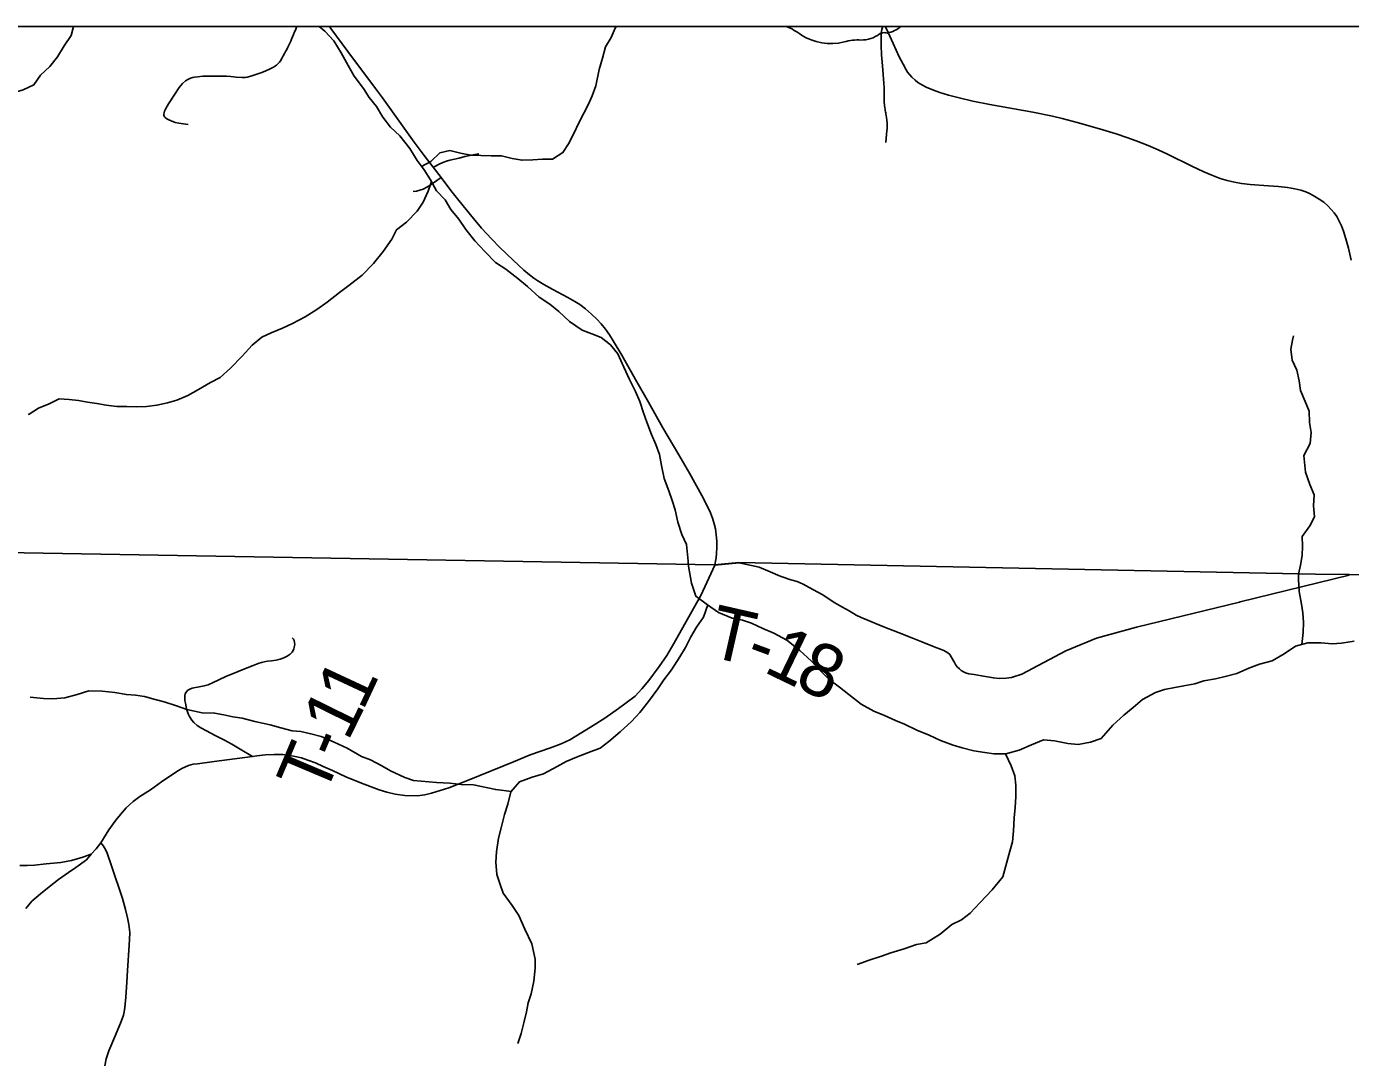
# Model space of a CAD drawing. Extents: x 0 to 191, y 0 to 55.
# Drawn here: x 186.002 to 187.422, y 53.609 to 54.72 of the extents above; entities that cross this region are included whole.
import ezdxf

# ---------------------------------------------------------------- set-up
doc = ezdxf.new("R2010")
doc.units = 0
for name, color, linetype in [('GM_X_Corporation', 7, 'Continuous'), ('GM_X_County_Road', 7, 'Continuous'), ('GM_X_Minor_River', 7, 'Continuous'), ('GM_X_State_Route', 7, 'Continuous'), ('GM_X_Township_Road', 7, 'Continuous'), ('GM_X_Township_Road_Text', 7, 'Continuous'), ('GM_X_Unincorporated', 7, 'Continuous')]:
    doc.layers.add(name, color=color, linetype=linetype)

msp = doc.modelspace()

# ---------------------------------------------------------------- linework, layer by layer
at = {"layer": 'GM_X_Corporation'}
msp.add_lwpolyline([(190.454, 54.7197), (184.1701, 54.7197), (184.1701, 53.923), (184.4114, 53.9192), (184.4129, 54.1665), (185.8476, 54.1564), (185.8681, 54.1568), (185.9791, 54.1551), (186.7401, 54.1422), (186.7662, 54.1447), (187.3845, 54.1319), (187.4205, 54.1315), (187.8766, 54.1257), (188.8023, 54.11), (189.605, 54.0923), (189.9218, 54.091), (189.9868, 54.0885), (190.0713, 54.0857), (190.1339, 54.0854), (190.3547, 54.0823), (190.439, 54.0815), (190.4406, 54.1842), (190.4414, 54.2285), (190.4414, 54.232)], close=True, dxfattribs=at)
msp.add_lwpolyline([(190.454, 54.7197), (184.1701, 54.7197), (184.1701, 53.923), (184.4114, 53.9192), (184.4129, 54.1665), (185.8476, 54.1564), (185.8681, 54.1568), (185.9791, 54.1551), (186.7401, 54.1422), (186.7662, 54.1447), (187.3845, 54.1319), (187.4205, 54.1315), (187.8766, 54.1257), (188.8023, 54.11), (189.605, 54.0923), (189.9218, 54.091), (189.9868, 54.0885), (190.0713, 54.0857), (190.1339, 54.0854), (190.3547, 54.0823), (190.439, 54.0815), (190.4406, 54.1842), (190.4414, 54.2285), (190.4414, 54.232)], close=True, dxfattribs=at)
for points in [[(187.8766, 54.1257), (187.4205, 54.1315), (187.3845, 54.1319), (186.7662, 54.1447), (186.7401, 54.1422), (185.9791, 54.1551), (185.8681, 54.1568), (185.8476, 54.1564), (184.4129, 54.1665), (184.4114, 53.9192), (184.1701, 53.923), (184.1701, 47.9197)], [(184.8319, 50.3472), (184.8438, 50.7018), (184.8438, 50.7041), (184.8504, 51.1664), (184.8504, 51.1691), (184.8564, 51.468), (185.0493, 51.466), (185.0519, 51.466), (185.737, 51.4587), (185.8223, 51.4579), (185.8471, 52.9493), (185.8472, 52.953), (185.8634, 53.9305), (185.8653, 54.0182), (185.8655, 54.0321), (185.8681, 54.1568), (185.9791, 54.1551), (186.7401, 54.1422), (186.7662, 54.1447), (187.3845, 54.1319), (187.4205, 54.1315), (187.8766, 54.1257)]]:
    msp.add_lwpolyline(points, dxfattribs=at)
at = {"layer": 'GM_X_County_Road'}
msp.add_line((186.4469, 54.5577), (186.4385, 54.5686), dxfattribs=at)
for points in [[(186.4385, 54.5686), (186.4288, 54.5812), (186.4181, 54.5957), (186.3839, 54.6431), (186.3765, 54.653), (186.3469, 54.693), (186.3288, 54.7175), (186.3273, 54.7197)], [(186.7403, 54.1417), (186.7412, 54.1461), (186.7417, 54.1494), (186.7423, 54.1542), (186.7426, 54.1605), (186.7425, 54.1674), (186.7419, 54.1743), (186.741, 54.1805), (186.7397, 54.186), (186.7379, 54.192), (186.7356, 54.1978), (186.7311, 54.2075), (186.7266, 54.2164), (186.7134, 54.2403), (186.7084, 54.249), (186.7017, 54.2602), (186.6961, 54.2698), (186.6848, 54.2891), (186.6693, 54.3167), (186.6553, 54.3409), (186.6406, 54.3669), (186.6315, 54.3825), (186.6274, 54.3888), (186.6231, 54.3949), (186.6184, 54.4008), (186.6137, 54.4058), (186.6083, 54.411), (186.6016, 54.4167), (186.5956, 54.4212), (186.5904, 54.4246), (186.5828, 54.429), (186.5668, 54.4374), (186.5571, 54.4428), (186.5507, 54.4466), (186.5462, 54.4498), (186.5418, 54.4531), (186.5356, 54.4583), (186.5242, 54.4688), (186.5095, 54.483), (186.5012, 54.4914), (186.4903, 54.5033), (186.4815, 54.5137), (186.4658, 54.5329), (186.4575, 54.5438), (186.4469, 54.5577)], [(186.082, 53.8438), (186.0907, 53.8578), (186.098, 53.868), (186.1032, 53.8742), (186.1091, 53.8814), (186.1168, 53.8881), (186.124, 53.8935), (186.1352, 53.9007), (186.1471, 53.9091), (186.1634, 53.9202), (186.1689, 53.9235), (186.1759, 53.9266), (186.1812, 53.928), (186.1858, 53.9286), (186.2036, 53.9311), (186.2448, 53.9365), (186.2493, 53.937), (186.2585, 53.9382), (186.268, 53.9387), (186.2772, 53.9385), (186.2888, 53.9366), (186.2971, 53.9349), (186.304, 53.9326), (186.3123, 53.9296), (186.3203, 53.9257), (186.3304, 53.9212), (186.3449, 53.9146), (186.3614, 53.9077), (186.3805, 53.9006), (186.3886, 53.898), (186.3978, 53.896), (186.408, 53.8944), (186.4214, 53.8943), (186.4293, 53.8954), (186.4365, 53.8971), (186.455, 53.9026), (186.4771, 53.9114), (186.5245, 53.9307), (186.5425, 53.938), (186.5642, 53.9456), (186.5757, 53.9501), (186.5849, 53.9544), (186.5979, 53.9622), (186.61, 53.9698), (186.6224, 53.9776), (186.6371, 53.988), (186.6454, 53.9938), (186.6548, 54.0013), (186.6622, 54.0091), (186.6696, 54.0178), (186.6807, 54.0328), (186.6888, 54.0446), (186.6965, 54.0577), (186.7048, 54.0723), (186.7253, 54.1092), (186.7403, 54.1417)], [(186.0017, 53.7734), (186.0082, 53.781), (186.0172, 53.7892), (186.0267, 53.7967), (186.0366, 53.8044), (186.0472, 53.812), (186.0551, 53.8172), (186.0665, 53.8255), (186.0718, 53.8315), (186.0771, 53.8373), (186.082, 53.8438)], [(186.0718, 53.8315), (186.0627, 53.8283), (186.0506, 53.8249), (186.0391, 53.8228), (186.0235, 53.8212), (186.011, 53.8198), (186.003, 53.8194), (185.9951, 53.8196)]]:
    msp.add_lwpolyline(points, dxfattribs=at)
at = {"layer": 'GM_X_Minor_River'}
for points in [[(186.0526, 54.7197), (186.0502, 54.71), (186.0428, 54.6989), (186.0357, 54.6871), (186.0275, 54.6767), (186.0174, 54.6675), (186.0103, 54.6572), (185.9986, 54.6517), (185.9869, 54.6481), (185.9745, 54.6415), (185.9621, 54.6357), (185.9523, 54.6318), (185.9413, 54.6286), (185.9229, 54.6204), (185.9108, 54.6134), (185.9, 54.6023), (185.8925, 54.5889), (185.8801, 54.5808), (185.8681, 54.5738), (185.8568, 54.5645), (185.8535, 54.5603)], [(186.3162, 54.7197), (186.3223, 54.7146), (186.3319, 54.7041), (186.3396, 54.6913), (186.3473, 54.6777), (186.3538, 54.6664), (186.3638, 54.6533), (186.3699, 54.6435), (186.3776, 54.6337), (186.3845, 54.6224), (186.3926, 54.6115), (186.4025, 54.6022), (186.4132, 54.5886), (186.4213, 54.5759), (186.4286, 54.5657), (186.4355, 54.5552), (186.4421, 54.5435), (186.4513, 54.5337), (186.4574, 54.5232), (186.4658, 54.513), (186.4735, 54.5018), (186.4831, 54.4897), (186.4938, 54.4781), (186.5053, 54.4665), (186.5163, 54.4594), (186.5293, 54.4493), (186.5396, 54.4407), (186.5522, 54.4291), (186.5636, 54.4217), (186.5732, 54.4139), (186.5846, 54.403), (186.598, 54.3937), (186.6086, 54.39), (186.6185, 54.386), (186.6284, 54.3781), (186.6365, 54.3684), (186.6427, 54.354), (186.6489, 54.3408), (186.6554, 54.328), (186.6601, 54.3174), (186.664, 54.3053), (186.6675, 54.2951), (186.6725, 54.2819), (186.6772, 54.271), (186.6811, 54.2604), (186.6831, 54.2486), (186.6859, 54.2346), (186.6909, 54.2214), (186.6948, 54.2112)], [(186.4258, 54.5696), (186.4357, 54.5749), (186.4455, 54.5841), (186.4564, 54.5865), (186.4678, 54.5836), (186.4788, 54.5815), (186.4894, 54.5813), (186.5004, 54.581), (186.5117, 54.5808), (186.5231, 54.5779), (186.5337, 54.5761), (186.5454, 54.5767), (186.5556, 54.5772), (186.5662, 54.5773), (186.5775, 54.5843), (186.5835, 54.5938), (186.589, 54.6042), (186.595, 54.6171), (186.6046, 54.6355), (186.6087, 54.6454), (186.6127, 54.6561), (186.6164, 54.6736), (186.62, 54.6858), (186.6233, 54.6979), (186.6292, 54.7079), (186.6337, 54.7178), (186.6348, 54.7197)], [(186.4366, 54.5532), (186.433, 54.543), (186.4278, 54.5312), (186.4211, 54.5216), (186.4099, 54.5097), (186.399, 54.5016), (186.3942, 54.4916), (186.3848, 54.4782), (186.3744, 54.4652), (186.3624, 54.4529), (186.3481, 54.4417), (186.338, 54.4344), (186.3248, 54.424), (186.3136, 54.4159), (186.3012, 54.4081), (186.2876, 54.4011), (186.2767, 54.3961), (186.2646, 54.391), (186.2545, 54.3863), (186.2443, 54.3778), (186.2335, 54.3659), (186.2211, 54.3529), (186.2099, 54.3432), (186.1997, 54.3378), (186.1869, 54.33), (186.1752, 54.3238), (186.1636, 54.3187), (186.1534, 54.316), (186.1421, 54.3132), (186.1311, 54.3119), (186.1201, 54.3117), (186.1099, 54.312), (186.0993, 54.3119), (186.0879, 54.3132), (186.0777, 54.315), (186.0678, 54.3164), (186.058, 54.3182), (186.0481, 54.3196), (186.0375, 54.3202), (186.0266, 54.3147), (186.0153, 54.31), (186.0052, 54.3038), (186.004, 54.3034)], [(187.3663, 54.1319), (187.3684, 54.1417), (187.37, 54.152), (187.3704, 54.1621), (187.3703, 54.1723), (187.3785, 54.1838), (187.3833, 54.1937), (187.3824, 54.2055), (187.3831, 54.2173), (187.3784, 54.2282), (187.3738, 54.2414), (187.3721, 54.2592), (187.3787, 54.2722), (187.3798, 54.284), (187.3781, 54.2946), (187.3776, 54.3068), (187.3734, 54.3173), (187.3683, 54.329), (187.3671, 54.3396), (187.3643, 54.351), (187.3593, 54.3616), (187.358, 54.3733), (187.3598, 54.3832), (187.3609, 54.3878)], [(186.6948, 54.2112), (186.6979, 54.201), (186.7007, 54.1878), (186.705, 54.1745), (186.7101, 54.164), (186.7118, 54.1459), (186.7122, 54.1407)], [(186.7122, 54.1407), (186.7152, 54.1223), (186.7201, 54.1083), (186.7327, 54.0992), (186.7444, 54.0909), (186.7589, 54.0849), (186.7699, 54.0826), (186.7798, 54.0796), (186.7919, 54.0736), (186.8037, 54.0687), (186.8177, 54.0611), (186.8314, 54.0502), (186.844, 54.0388), (186.8531, 54.029), (186.863, 54.0191), (186.874, 54.0108), (186.8839, 54.0029), (186.8972, 53.9927), (186.9109, 53.9851), (186.9223, 53.9802), (186.9341, 53.9749), (186.9436, 53.9712), (186.9569, 53.9648), (186.9701, 53.9591), (186.9823, 53.9535), (186.996, 53.9486), (187.0055, 53.9456), (187.018, 53.9426), (187.0298, 53.9407), (187.0396, 53.9392), (187.0525, 53.9393), (187.0666, 53.9431), (187.0798, 53.9489), (187.0927, 53.9542), (187.1045, 53.9531), (187.1189, 53.9505), (187.1299, 53.9494), (187.1432, 53.9518), (187.1546, 53.9556), (187.1671, 53.9701), (187.1788, 53.9807), (187.189, 53.9888), (187.1989, 53.9975), (187.2129, 54.0052), (187.2224, 54.0082), (187.2337, 54.0106), (187.2432, 54.0121), (187.255, 54.0144), (187.2648, 54.0175), (187.2774, 54.0198), (187.2876, 54.0221), (187.3001, 54.0256), (187.313, 54.031), (187.3244, 54.0356), (187.338, 54.039), (187.3509, 54.0467), (187.363, 54.0547), (187.3763, 54.0585), (187.3907, 54.0582), (187.4025, 54.0571), (187.4123, 54.0579), (187.426, 54.0602)], [(187.3697, 54.0566), (187.3713, 54.0695), (187.3717, 54.0802), (187.3709, 54.0904), (187.3694, 54.0999), (187.3671, 54.1136), (187.3663, 54.1265), (187.3663, 54.1319)], [(186.7328, 54.0991), (186.7281, 54.0859), (186.7206, 54.0752), (186.7145, 54.0649), (186.7089, 54.0535), (186.7028, 54.0433), (186.6941, 54.0292), (186.6858, 54.0185), (186.6794, 54.009), (186.6692, 53.9953), (186.6601, 53.9835), (186.651, 53.974), (186.6389, 53.9629), (186.6268, 53.9526), (186.6173, 53.9453), (186.6048, 53.9407), (186.5919, 53.9358), (186.5809, 53.9312), (186.5714, 53.9258), (186.5567, 53.9178), (186.5445, 53.9143), (186.5309, 53.9093), (186.5218, 53.8983), (186.5184, 53.8854), (186.515, 53.874), (186.5113, 53.8599), (186.5086, 53.8489), (186.5064, 53.834), (186.5057, 53.823), (186.5068, 53.8097), (186.5103, 53.7991), (186.5133, 53.7896), (186.5232, 53.7764), (186.5301, 53.7658), (186.5366, 53.751), (186.5442, 53.7354), (186.5476, 53.7191), (186.5477, 53.7092), (186.5462, 53.6955), (186.5436, 53.6819), (186.5402, 53.672), (186.5383, 53.6625), (186.5357, 53.6507), (186.5327, 53.6393), (186.5293, 53.6286)], [(186.5222, 53.8988), (186.5055, 53.9009), (186.4815, 53.9061), (186.4683, 53.9065), (186.4561, 53.9076), (186.4421, 53.9086), (186.4174, 53.9105), (186.4079, 53.9138), (186.3927, 53.921), (186.3832, 53.9263), (186.3711, 53.9327), (186.3616, 53.9365), (186.346, 53.9452), (186.3323, 53.9519), (186.3183, 53.958), (186.3072, 53.9606), (186.2966, 53.9632), (186.2871, 53.9639), (186.275, 53.9673), (186.2636, 53.9703), (186.2473, 53.9741), (186.2336, 53.9774), (186.2237, 53.9789), (186.2139, 53.9812), (186.204, 53.983), (186.1907, 53.9834), (186.1744, 53.9867), (186.163, 53.9909), (186.1501, 53.995), (186.1402, 53.9976), (186.1288, 54.0006), (186.1193, 54.0021), (186.1094, 54.0028), (186.0969, 54.0051), (186.0833, 54.0065), (186.0692, 54.0069), (186.0567, 54.003), (186.0434, 53.9992), (186.0305, 53.9984), (186.0207, 53.9987), (186.0062, 54.0002)], [(187.0522, 53.9393), (187.0583, 53.9264), (187.0621, 53.9158), (187.0632, 53.9055), (187.0633, 53.8934), (187.0625, 53.8816), (187.0614, 53.8706), (187.0607, 53.8565), (187.0596, 53.8447), (187.0566, 53.8348), (187.0524, 53.8189), (187.0491, 53.8071), (187.0377, 53.7934), (187.0248, 53.7796), (187.0142, 53.7682), (187.0048, 53.761), (186.9945, 53.756), (186.9821, 53.7457), (186.9669, 53.7365), (186.9567, 53.7346), (186.9434, 53.73), (186.929, 53.7257), (186.9191, 53.7223), (186.9059, 53.7177), (186.893, 53.7131)]]:
    msp.add_lwpolyline(points, dxfattribs=at)
at = {"layer": 'GM_X_State_Route'}
msp.add_lwpolyline([(187.4227, 54.4691), (187.4198, 54.4818), (187.4171, 54.4919), (187.4146, 54.5002), (187.4124, 54.5059), (187.41, 54.5109), (187.4072, 54.5157), (187.4044, 54.5197), (187.4013, 54.5234), (187.3975, 54.5274), (187.3933, 54.531), (187.3884, 54.5345), (187.3821, 54.5384), (187.3779, 54.5406), (187.374, 54.5422), (187.3688, 54.5439), (187.3622, 54.5455), (187.3544, 54.5469), (187.3446, 54.548), (187.3342, 54.5487), (187.3144, 54.5503), (187.3051, 54.5513), (187.2977, 54.5525), (187.2898, 54.5543), (187.2821, 54.5567), (187.2733, 54.56), (187.2648, 54.5637), (187.2519, 54.5699), (187.2258, 54.5828), (187.2157, 54.5875), (187.2049, 54.5921), (187.1922, 54.597), (187.1823, 54.6006), (187.1706, 54.6045), (187.1528, 54.6098), (187.1289, 54.6166), (187.1127, 54.6209), (187.1025, 54.6233), (187.0812, 54.6276), (187.0354, 54.636), (187.0171, 54.6397), (187.0025, 54.643), (186.9911, 54.6461), (186.9816, 54.649), (186.975, 54.6513), (186.9669, 54.6547), (186.963, 54.6567), (186.9582, 54.6596), (186.9553, 54.662), (186.9515, 54.6653), (186.9471, 54.6707), (186.9454, 54.6733), (186.9422, 54.6794), (186.9382, 54.6871), (186.9317, 54.7013), (186.9279, 54.7092), (186.9247, 54.7164), (186.9232, 54.7197)], dxfattribs=at)
at = {"layer": 'GM_X_Township_Road'}
msp.add_line((187.3038, 54.1023), (187.4207, 54.131), dxfattribs=at)
for points in [[(186.1756, 54.6146), (186.1707, 54.6153), (186.1657, 54.616), (186.1619, 54.6168), (186.1573, 54.6183), (186.1548, 54.6195), (186.1528, 54.6206), (186.1511, 54.6219), (186.1504, 54.6226), (186.15, 54.6234), (186.1497, 54.6244), (186.1496, 54.6256), (186.1498, 54.6269), (186.1504, 54.6288), (186.1513, 54.631), (186.1547, 54.6366), (186.1614, 54.6471), (186.1662, 54.6543), (186.1697, 54.6584), (186.1729, 54.6613), (186.1754, 54.6627), (186.1783, 54.6641), (186.1806, 54.6648), (186.1824, 54.6652), (186.1862, 54.6658), (186.1915, 54.6663), (186.1967, 54.6665), (186.2109, 54.6665), (186.2168, 54.6662), (186.2214, 54.6659), (186.2272, 54.6653), (186.2335, 54.6649), (186.2372, 54.6651), (186.2391, 54.6653), (186.2427, 54.6662), (186.2494, 54.6686), (186.2545, 54.6703), (186.259, 54.672), (186.263, 54.6738), (186.2673, 54.6761), (186.2703, 54.6781), (186.2719, 54.6797), (186.2735, 54.6815), (186.2746, 54.6829), (186.2765, 54.6859), (186.2776, 54.6881), (186.279, 54.6906), (186.2801, 54.6927), (186.2814, 54.6951), (186.2827, 54.6976), (186.2839, 54.7002), (186.2856, 54.704), (186.2865, 54.7061), (186.2887, 54.7112), (186.2898, 54.7138), (186.2906, 54.7158), (186.2915, 54.7179), (186.2922, 54.7197)], [(186.9239, 54.5951), (186.9246, 54.6041), (186.9249, 54.6076), (186.9251, 54.6103), (186.9252, 54.6131), (186.9251, 54.6158), (186.9248, 54.6192), (186.9245, 54.6221), (186.9242, 54.624), (186.9239, 54.6256), (186.9237, 54.6269), (186.9235, 54.6281), (186.9232, 54.6294), (186.923, 54.6307), (186.9226, 54.6328), (186.9224, 54.6346), (186.9222, 54.636), (186.9221, 54.6376), (186.922, 54.6392), (186.922, 54.6408), (186.922, 54.6422), (186.922, 54.6441), (186.9218, 54.654), (186.9216, 54.6588), (186.9203, 54.6775), (186.9192, 54.6893), (186.9187, 54.6992), (186.9186, 54.7073), (186.9187, 54.7101), (186.919, 54.7129), (186.9192, 54.7148), (186.9196, 54.7165), (186.9201, 54.7186), (186.9204, 54.7194), (186.9205, 54.7197)], [(186.4385, 54.5686), (186.44, 54.5693), (186.4448, 54.5719), (186.4489, 54.5737), (186.4526, 54.575), (186.4562, 54.5761), (186.4663, 54.5785), (186.4723, 54.58), (186.4778, 54.5813), (186.4831, 54.5823), (186.4873, 54.583)], [(186.4168, 54.5426), (186.4205, 54.5431), (186.4242, 54.5439), (186.4277, 54.5452), (186.4316, 54.5472), (186.4363, 54.5502), (186.4424, 54.5545), (186.4469, 54.5577)], [(186.7403, 54.1417), (186.7664, 54.1442), (186.7879, 54.1397), (186.7999, 54.1347), (186.8049, 54.1323), (186.8086, 54.1306), (186.8127, 54.129), (186.8219, 54.1261), (186.8285, 54.124), (186.8351, 54.1212), (186.8415, 54.1178), (186.8555, 54.1101), (186.8691, 54.1014), (186.8764, 54.0971), (186.8843, 54.0926), (186.8921, 54.088), (186.8973, 54.0855), (186.9034, 54.0829), (186.9207, 54.0757), (186.9382, 54.0689), (186.9533, 54.063), (186.9623, 54.0593), (186.9739, 54.0548), (186.9861, 54.05), (186.9901, 54.0477), (186.9923, 54.0457), (186.9939, 54.0435), (186.9973, 54.0374), (186.9988, 54.0343), (187.0007, 54.0321), (187.0026, 54.0303), (187.0046, 54.0288), (187.007, 54.0273), (187.0093, 54.0262), (187.0129, 54.0251), (187.0186, 54.0242), (187.0264, 54.023), (187.0391, 54.0207), (187.0454, 54.0202), (187.0529, 54.0203), (187.0586, 54.021), (187.0695, 54.0249), (187.1166, 54.0498), (187.1497, 54.0632), (187.1926, 54.075), (187.3029, 54.102), (187.3038, 54.1023)], [(186.2448, 53.9365), (186.2315, 53.9442), (186.2226, 53.9496), (186.2145, 53.9538), (186.209, 53.9567), (186.2047, 53.959), (186.1953, 53.9639), (186.1893, 53.9672), (186.1854, 53.9698), (186.1818, 53.9728), (186.1795, 53.9754), (186.177, 53.9792), (186.1757, 53.9823), (186.1744, 53.9863), (186.1736, 53.9896), (186.1727, 53.9936), (186.1722, 53.9965), (186.1721, 53.9998), (186.1722, 54.0018), (186.1726, 54.0038), (186.1736, 54.0055), (186.1753, 54.0074), (186.1774, 54.0086), (186.1798, 54.0097), (186.1818, 54.0101), (186.1873, 54.011), (186.1929, 54.0121), (186.1971, 54.0134), (186.2019, 54.0156), (186.2162, 54.0223), (186.2425, 54.0329), (186.2453, 54.0342), (186.2489, 54.0355), (186.2518, 54.0366), (186.2544, 54.0373), (186.2571, 54.0379), (186.2607, 54.0385), (186.2652, 54.0391), (186.2702, 54.0399), (186.2744, 54.0409), (186.2784, 54.0423), (186.2819, 54.044), (186.2851, 54.0463), (186.2871, 54.0485), (186.2889, 54.0516), (186.2895, 54.0538), (186.2899, 54.0566), (186.2898, 54.0587), (186.2895, 54.0608), (186.2886, 54.0624), (186.2873, 54.0636)], [(186.0864, 53.6045), (186.0877, 53.6119), (186.0907, 53.6207), (186.0979, 53.6374), (186.104, 53.6522), (186.1062, 53.659), (186.107, 53.6625), (186.1077, 53.6669), (186.1089, 53.6783), (186.1098, 53.6943), (186.1108, 53.7067), (186.1124, 53.7341), (186.1128, 53.7402), (186.113, 53.7474), (186.1121, 53.7562), (186.1107, 53.7634), (186.1085, 53.7722), (186.1053, 53.7839), (186.0939, 53.8179), (186.0889, 53.8326), (186.087, 53.8367), (186.085, 53.8403), (186.082, 53.8438)]]:
    msp.add_lwpolyline(points, dxfattribs=at)
at = {"layer": 'GM_X_Unincorporated'}
msp.add_line((186.9398, 54.7197), (186.8171, 54.7197), dxfattribs=at)
for centre, major_axis, start_param, end_param in [((186.7796, 54.6641), (0.079, 0), 0.823519, 1.076306), ((186.9186, 54.7346), (0.0282, 0), 4.937069, 5.563142), ((186.865, 54.7415), (0.0501, 0), 4.026481, 4.996735), ((186.894, 54.6723), (0.0412, 0), 1.495662, 1.94098), ((186.8976, 54.7265), (0.0267, 0), 4.691044, 5.507374), ((186.9218, 54.7071), (0.00752, 0), 1.147584, 2.315152)]:
    msp.add_ellipse(centre, major_axis=major_axis, ratio=0.8, start_param=start_param, end_param=end_param, dxfattribs=at)

# ---------------------------------------------------------------- texts
at = {"layer": 'GM_X_Township_Road_Text'}
for s, rotation, p in [('T', 347.2039, (186.7311, 54.0443)), ('1', 334.2402, (186.7912, 54.0278)), ('-', 339.5801, (186.7706, 54.0354)), ('8', 335.6277, (186.8241, 54.012)), ('1', 65.0078, (186.3629, 53.9843)), ('1', 63.7584, (186.3468, 53.9517)), ('T', 67.0788, (186.3215, 53.8918)), ('-', 67.0433, (186.3381, 53.931))]:
    msp.add_text(s, height=0.0568, rotation=rotation, dxfattribs=at).set_placement(p)

doc.saveas('drawing.dxf')
